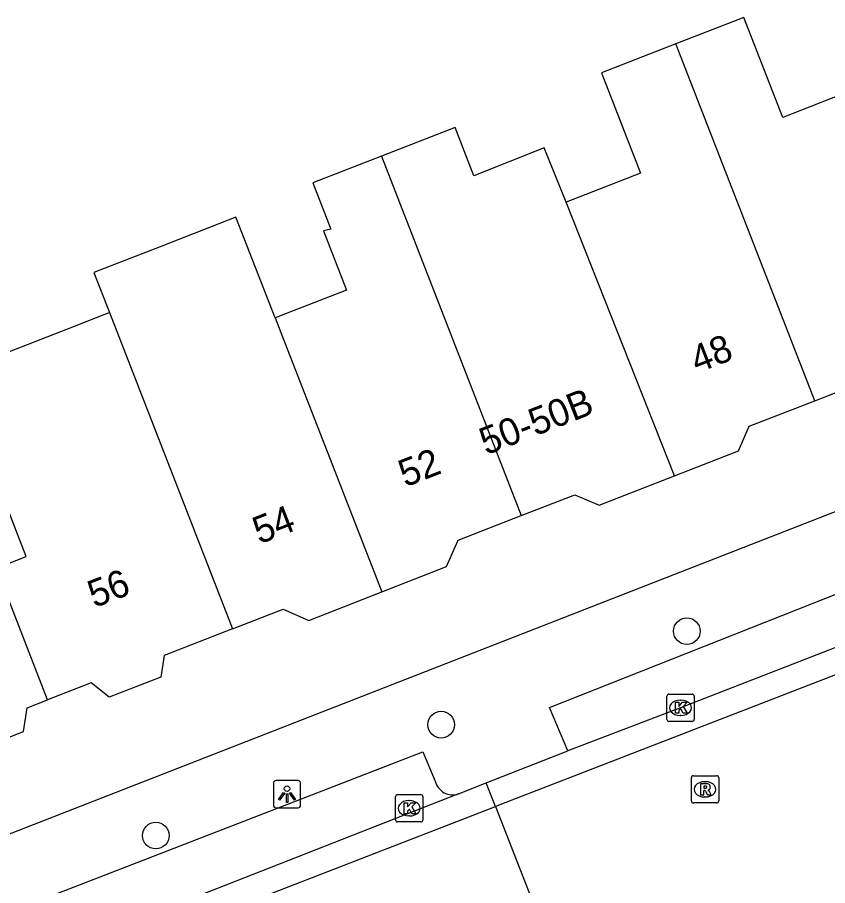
# Model space of a CAD drawing. Extents: x 161696 to 162377, y 380761 to 381673.
# Drawn here: x 161809.93 to 161839.62, y 381183.08 to 381214.87 of the extents above; entities that cross this region are included whole.
import ezdxf

# ---------------------------------------------------------------- set-up
doc = ezdxf.new("R2010")
doc.units = 0
for name, color, linetype in [('IMGEO_Boom', 7, 'Continuous'), ('IMGEO_Kolk', 7, 'Continuous'), ('IMGEO_Lichtpunt', 7, 'Continuous'), ('IMGEO_Pand', 7, 'Continuous'), ('IMGEO_Pand_nummerreeks', 7, 'Continuous'), ('IMGEO_Rijbaan_lokaal_open', 7, 'Continuous'), ('IMGEO_Rioolput', 7, 'Continuous'), ('IMGEO_Voetpad_open', 7, 'Continuous')]:
    doc.layers.add(name, color=color, linetype=linetype)

msp = doc.modelspace()

# ---------------------------------------------------------------- linework, layer by layer
at = {"layer": 'IMGEO_Boom'}
for centre in [(161834.462, 381192.395), (161825.462, 381188.973), (161815.005, 381184.911)]:
    msp.add_circle(centre, 0.489, dxfattribs=at)
at = {"layer": 'IMGEO_Kolk'}
for p, q in [((161833.806, 381190.091), (161834.658, 381190.091)), ((161833.731, 381189.165), (161833.731, 381190.017)), ((161834.219, 381189.871), (161834.244, 381189.871)), ((161834.732, 381190.017), (161834.732, 381189.165)), ((161834.658, 381189.091), (161833.806, 381189.091)), ((161834.242, 381189.311), (161834.217, 381189.311)), ((161823.789, 381185.484), (161823.789, 381186.336)), ((161823.864, 381186.41), (161824.716, 381186.41)), ((161824.79, 381186.336), (161824.79, 381185.484)), ((161824.277, 381186.19), (161824.302, 381186.19)), ((161824.3, 381185.63), (161824.275, 381185.63)), ((161824.716, 381185.41), (161823.864, 381185.41))]:
    msp.add_line(p, q, dxfattribs=at)
for points in [[(161833.806, 381190.091), (161834.658, 381190.091)], [(161833.731, 381189.165), (161833.731, 381190.017)], [(161834.052, 381189.791), (161834.175, 381189.791), (161834.175, 381189.64), (161834.305, 381189.791), (161834.469, 381189.791), (161834.323, 381189.64), (161834.476, 381189.391), (161834.324, 381189.391), (161834.239, 381189.555), (161834.175, 381189.488), (161834.175, 381189.391), (161834.052, 381189.391), (161834.052, 381189.791)], [(161834.732, 381190.017), (161834.732, 381189.165)], [(161834.658, 381189.091), (161833.806, 381189.091)], [(161823.789, 381185.484), (161823.789, 381186.336)], [(161823.864, 381186.41), (161824.716, 381186.41)], [(161824.79, 381186.336), (161824.79, 381185.484)], [(161824.11, 381186.11), (161824.233, 381186.11), (161824.233, 381185.959), (161824.363, 381186.11), (161824.527, 381186.11), (161824.381, 381185.959), (161824.534, 381185.71), (161824.382, 381185.71), (161824.297, 381185.874), (161824.233, 381185.807), (161824.233, 381185.71), (161824.11, 381185.71), (161824.11, 381186.11)], [(161824.716, 381185.41), (161823.864, 381185.41)]]:
    msp.add_lwpolyline(points, dxfattribs=at)
for centre, start, end in [((161833.808, 381190.015), 91.552, 178.448), ((161833.808, 381190.015), 91.552, 178.448), ((161834.656, 381190.015), 1.552, 88.448), ((161834.656, 381190.015), 1.552, 88.448), ((161833.808, 381189.167), 181.552, 268.448), ((161833.808, 381189.167), 181.552, 268.448), ((161834.656, 381189.167), 271.552, 358.448), ((161834.656, 381189.167), 271.552, 358.448), ((161823.866, 381186.334), 91.552, 178.448), ((161823.866, 381186.334), 91.552, 178.448), ((161824.714, 381186.334), 1.552, 88.448), ((161824.714, 381186.334), 1.552, 88.448), ((161823.866, 381185.486), 181.552, 268.448), ((161823.866, 381185.486), 181.552, 268.448), ((161824.714, 381185.486), 271.552, 358.448), ((161824.714, 381185.486), 271.552, 358.448)]:
    msp.add_arc(centre, 0.0765, start, end, dxfattribs=at)
for centre, major_axis, ratio, start_param, end_param in [((161834.218, 381189.591), (-0.387, 0.002), 0.722429, 4.712389, 7.853982), ((161834.243, 381189.591), (-0.39, 0.002), 0.717154, 1.570796, 4.712389), ((161824.276, 381185.91), (-0.387, 0.002), 0.722429, 4.712389, 7.853982), ((161824.301, 381185.91), (-0.39, 0.002), 0.717154, 1.570796, 4.712389)]:
    msp.add_ellipse(centre, major_axis=major_axis, ratio=ratio, start_param=start_param, end_param=end_param, dxfattribs=at)
at = {"layer": 'IMGEO_Lichtpunt'}
for p, q in [((161820.216, 381186.924), (161819.408, 381186.924)), ((161820.216, 381186.924), (161819.408, 381186.924)), ((161819.314, 381186.829), (161819.314, 381186.022)), ((161819.314, 381186.829), (161819.314, 381186.022)), ((161820.31, 381186.022), (161820.31, 381186.829)), ((161820.31, 381186.022), (161820.31, 381186.829)), ((161819.408, 381185.928), (161820.216, 381185.928)), ((161819.408, 381185.928), (161820.216, 381185.928))]:
    msp.add_line(p, q, dxfattribs=at)
for points in [[(161819.688, 381186.493), (161819.727, 381186.465), (161819.539, 381186.203), (161819.501, 381186.23), (161819.688, 381186.493)], [(161819.79, 381186.445), (161819.837, 381186.445), (161819.837, 381186.123), (161819.79, 381186.123), (161819.79, 381186.445)], [(161819.9, 381186.465), (161819.938, 381186.492), (161820.125, 381186.23), (161820.086, 381186.202), (161819.9, 381186.465)]]:
    msp.add_lwpolyline(points, dxfattribs=at)
msp.add_circle((161819.813, 381186.627), 0.0994, dxfattribs=at)
for centre, start, end in [((161819.408, 381186.829), 90, 180), ((161819.408, 381186.829), 90, 180), ((161820.216, 381186.829), 0, 90), ((161820.216, 381186.829), 0, 90), ((161819.408, 381186.022), 180, 270), ((161819.408, 381186.022), 180, 270), ((161820.216, 381186.022), 270, 0), ((161820.216, 381186.022), 270, 360)]:
    msp.add_arc(centre, 0.0946, start, end, dxfattribs=at)
at = {"layer": 'IMGEO_Pand'}
for points in [[(161840.782, 381212.298), (161837.983, 381211.208), (161836.555, 381214.872), (161834.062, 381213.901)], [(161834.062, 381213.901), (161831.331, 381212.838), (161832.764, 381209.161), (161830.038, 381208.099)], [(161839.15, 381200.834), (161834.062, 381213.901)], [(161830.038, 381208.099), (161829.238, 381210.096), (161826.664, 381209.064), (161825.972, 381210.838), (161823.27, 381209.786)], [(161823.27, 381209.786), (161820.76, 381208.808), (161821.417, 381207.122), (161821.145, 381207.054), (161821.989, 381204.886), (161819.378, 381203.869)], [(161823.27, 381209.786), (161828.393, 381196.626)], [(161834.01, 381198.084), (161830.038, 381208.099)], [(161819.378, 381203.869), (161817.943, 381207.555), (161815.23, 381206.498), (161812.739, 381205.527), (161813.308, 381204.064)], [(161807.125, 381201.655), (161812.022, 381203.563), (161813.014, 381203.949), (161813.308, 381204.064)], [(161813.308, 381204.064), (161817.816, 381192.481)], [(161819.378, 381203.869), (161819.735, 381202.951), (161823.285, 381193.834)], [(161839.15, 381200.834), (161841.213, 381201.638), (161842.078, 381201.258), (161844.686, 381202.274)], [(161811.04, 381189.88), (161809.161, 381194.704), (161810.258, 381195.131), (161808.6, 381199.389), (161808.077, 381199.185), (161807.125, 381201.655)], [(161834.01, 381198.084), (161836.35, 381198.995), (161836.747, 381199.898), (161839.15, 381200.834)], [(161828.393, 381196.626), (161830.364, 381197.394), (161831.245, 381197.007), (161834.01, 381198.084)], [(161823.285, 381193.834), (161825.659, 381194.759), (161826.084, 381195.726), (161828.393, 381196.626)], [(161817.816, 381192.481), (161819.674, 381193.205), (161820.612, 381192.792), (161823.285, 381193.834)], [(161817.816, 381192.481), (161815.316, 381191.507), (161815.195, 381190.716), (161813.293, 381189.975), (161812.636, 381190.501), (161811.04, 381189.88)], [(161804.969, 381188.325), (161805.268, 381187.558), (161807.638, 381188.481), (161808.26, 381187.983), (161810.158, 381188.723), (161810.291, 381189.588), (161811.04, 381189.88)]]:
    msp.add_lwpolyline(points, dxfattribs=at)
at = {"layer": 'IMGEO_Rijbaan_lokaal_open'}
for points in [[(161844.879, 381193.732), (161834.232, 381189.591), (161830.108, 381188.016)], [(161845.208, 381192.852), (161827.449, 381185.976)], [(161827.112, 381186.838), (161830.108, 381188.016)], [(161826.097, 381186.435), (161827.112, 381186.838)], [(161827.449, 381185.976), (161827.124, 381186.808), (161827.112, 381186.838)], [(161826.097, 381186.435), (161816.263, 381182.584), (161804.334, 381177.971), (161795.459, 381174.555), (161794.341, 381174.151)], [(161794.17, 381173.092), (161827.449, 381185.976)], [(161827.449, 381185.976), (161829.124, 381181.692)]]:
    msp.add_lwpolyline(points, dxfattribs=at)
at = {"layer": 'IMGEO_Rioolput'}
for p, q in [((161834.628, 381186.178), (161834.628, 381187.03)), ((161834.703, 381187.104), (161835.555, 381187.104)), ((161835.116, 381186.884), (161835.141, 381186.884)), ((161835.629, 381187.03), (161835.629, 381186.178)), ((161835.139, 381186.324), (161835.114, 381186.324)), ((161835.555, 381186.104), (161834.703, 381186.104))]:
    msp.add_line(p, q, dxfattribs=at)
for points in [[(161834.628, 381186.178), (161834.628, 381187.03)], [(161834.703, 381187.104), (161835.555, 381187.104)], [(161835.629, 381187.03), (161835.629, 381186.178)], [(161835.217, 381186.802), (161834.965, 381186.804), (161834.965, 381186.404)], [(161834.965, 381186.404), (161835.089, 381186.404), (161835.089, 381186.566), (161835.1, 381186.566)], [(161835.143, 381186.723), (161835.089, 381186.723), (161835.089, 381186.642)], [(161835.089, 381186.642), (161835.141, 381186.642)], [(161835.147, 381186.537), (161835.218, 381186.404), (161835.358, 381186.404), (161835.293, 381186.53)], [(161835.555, 381186.104), (161834.703, 381186.104)]]:
    msp.add_lwpolyline(points, dxfattribs=at)
for centre, radius, start, end in [((161834.705, 381187.028), 0.0765, 91.552, 178.448), ((161834.705, 381187.028), 0.0765, 91.552, 178.448), ((161835.553, 381187.028), 0.0765, 1.552, 88.448), ((161835.553, 381187.028), 0.0765, 1.552, 88.448), ((161835.099, 381186.513), 0.0533, 26.0293, 88.6989), ((161835.125, 381186.831), 0.19, 274.7715, 282.9687), ((161835.149, 381186.627), 0.0964, 77.0061, 93.1865), ((161835.163, 381186.684), 0.0378, 276.6634, 79.6772), ((161835.216, 381186.692), 0.109, 350.3612, 89.416), ((161835.214, 381186.692), 0.112, 277.5842, 350.9817), ((161835.198, 381186.477), 0.108, 29.5134, 73.7905), ((161834.705, 381186.18), 0.0765, 181.552, 268.448), ((161834.705, 381186.18), 0.0765, 181.552, 268.448), ((161835.553, 381186.18), 0.0765, 271.552, 358.448), ((161835.553, 381186.18), 0.0765, 271.552, 358.448)]:
    msp.add_arc(centre, radius, start, end, dxfattribs=at)
for centre, major_axis, ratio, start_param, end_param in [((161835.115, 381186.604), (-0.387, 0.002), 0.722429, 4.712389, 7.853982), ((161835.14, 381186.604), (-0.39, 0.002), 0.717154, 1.570796, 4.712389)]:
    msp.add_ellipse(centre, major_axis=major_axis, ratio=ratio, start_param=start_param, end_param=end_param, dxfattribs=at)
at = {"layer": 'IMGEO_Voetpad_open'}
for points in [[(161856.733, 381203.329), (161790.007, 381177.307), (161770.674, 381180.834)], [(161830.108, 381188.016), (161829.432, 381189.606), (161848.689, 381197.215), (161856.109, 381200.077), (161856.513, 381199.137)], [(161794.605, 381175.077), (161794.189, 381176.132), (161824.792, 381187.983), (161825.246, 381186.901)]]:
    msp.add_lwpolyline(points, dxfattribs=at)
msp.add_arc((161825.884, 381187.056), 0.656, 193.6269, 288.9636, dxfattribs=at)

# ---------------------------------------------------------------- texts
at = {"layer": 'IMGEO_Pand_nummerreeks'}
for s, rotation, p in [('48', 21.3199, (161834.84, 381201.831)), ('50-50B', 21.2906, (161827.108, 381198.83)), ('52', 21.3198, (161824.144, 381197.656)), ('54', 21.3198, (161818.802, 381195.571)), ('56', 21.0046, (161812.752, 381193.238))]:
    msp.add_text(s, height=1, rotation=rotation, dxfattribs=at).set_placement(p)

doc.saveas('drawing.dxf')
